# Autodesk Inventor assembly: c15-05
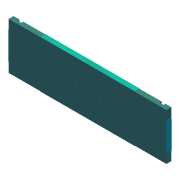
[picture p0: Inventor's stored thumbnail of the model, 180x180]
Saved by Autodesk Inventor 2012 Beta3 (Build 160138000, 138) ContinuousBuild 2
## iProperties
Created: 2011-02
Part Number: c15-05
Document SubType Name: Assembly
Designer: Beta-8540w
RuleStatus: InUse
Author: Beta-8540w
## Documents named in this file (4)
- C:\Inventor 2012 Essentials\Assemblies\Chapter 15\c15-05.iam
- C:\Inventor 2012 Essentials\Parts\Chapter 15\c15-18.ipt
- C:\Inventor 2012 Essentials\Parts\Chapter 15\c15-19.ipt
- C:\Inventor 2012 Essentials\Parts\Chapter 15\c15-20.ipt
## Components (5 placed, 3 different names)
1. c15-18:1 — Flush:3, Flush:6, Flush:9, Flush:12
2. c15-19:1 — Flush:3
3. c15-19:2 — Flush:6
4. c15-20:1 — Flush:9
5. c15-20:2 — Flush:12
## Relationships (4: Flush 4)
- Flush:3: c15-18:1 ↔ c15-19:1
- Flush:6: c15-18:1 ↔ c15-19:2
- Flush:9: c15-18:1 ↔ c15-20:1
- Flush:12: c15-18:1 ↔ c15-20:2
## Named parameters: drawer_width = 508 mm, drawer_height = 203.2 mm, pull_width = 76.2 mm
